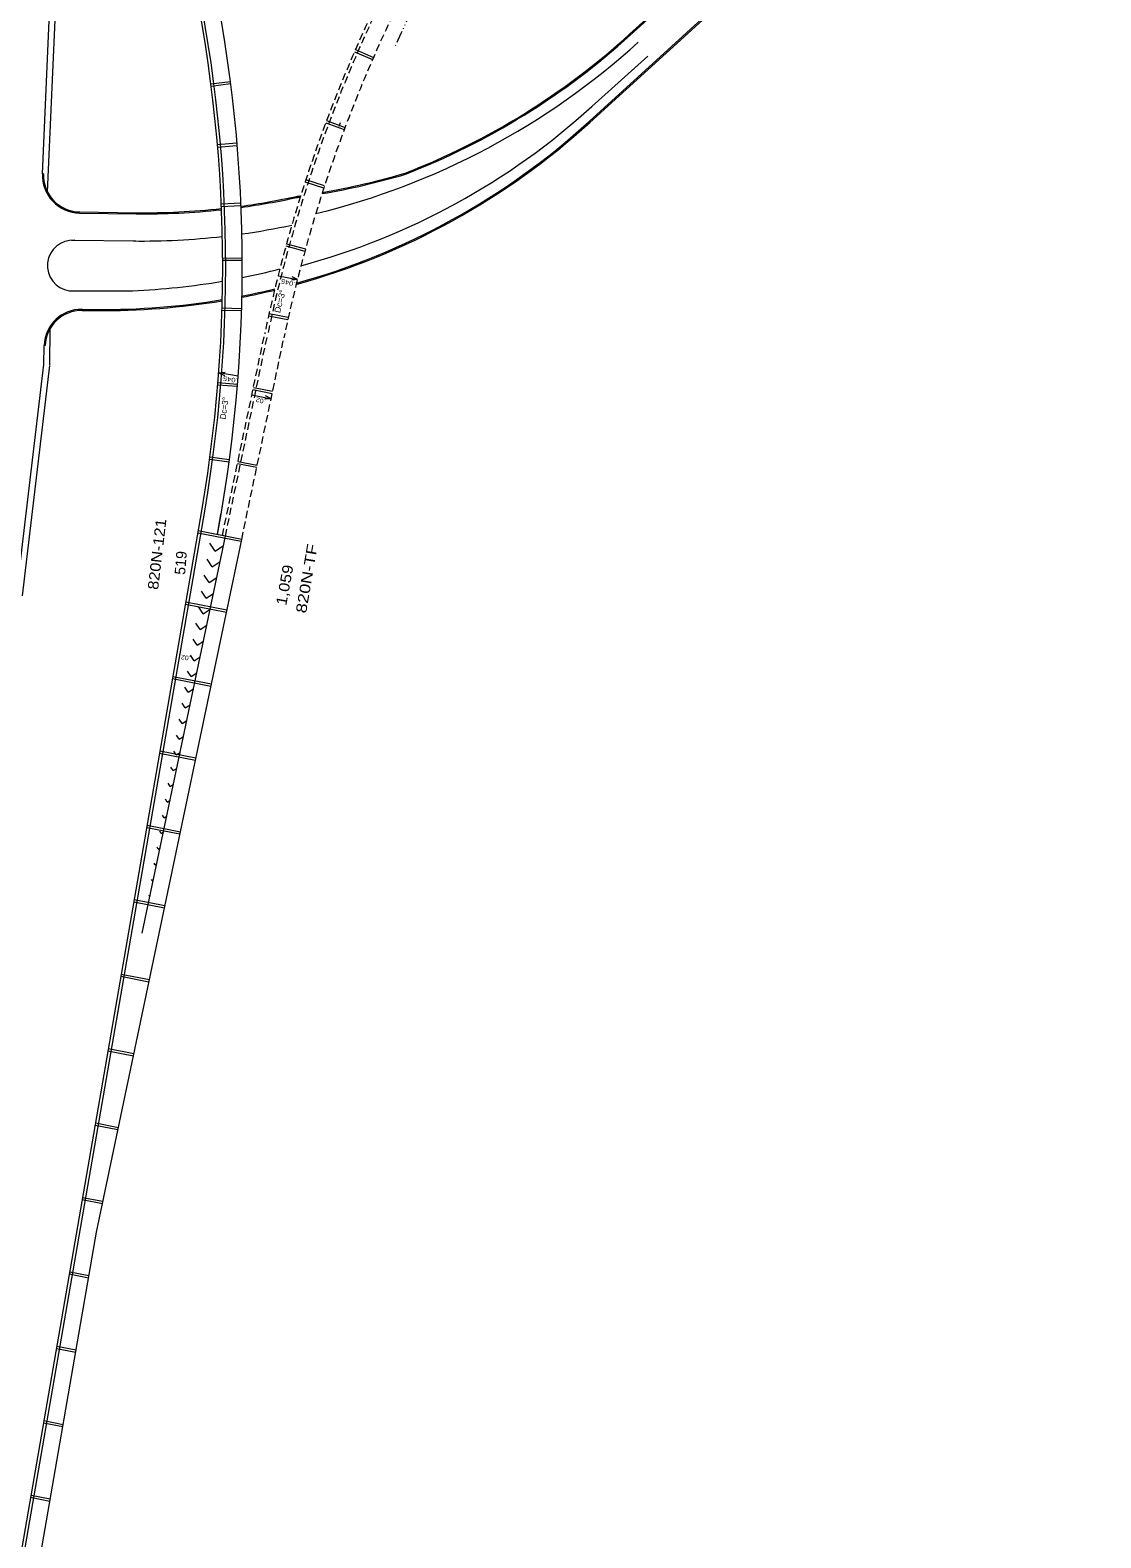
# Model space of a CAD drawing. Extents: x 2354993 to 2372084, y 6966390 to 6990057.
# Drawn here: x 2364667 to 2366085, y 6974745 to 6976742 of the extents above; entities that cross this region are included whole.
import ezdxf

# ---------------------------------------------------------------- set-up
doc = ezdxf.new("R2010")
doc.units = 0
doc.header["$LTSCALE"] = 3.2
doc.linetypes.add('DASH_DOUBLE_DOT', pattern=[9.2, 5, -1.2, 0.3, -1.2, 0.3, -1.2])
doc.linetypes.add('MEDIUM_DASHED', pattern=[4.5, 3, -1.5])
for name, color, linetype, lineweight in [('12', 7, 'Continuous', 13), ('13', 7, 'Continuous', 13), ('17', 7, 'Continuous', 13), ('19', 7, 'Continuous', 13), ('25', 7, 'Continuous', 13), ('4', 7, 'Continuous', 13), ('5', 7, 'Continuous', 13), ('60', 7, 'DASH_DOUBLE_DOT', 13), ('61', 7, 'Continuous', 13)]:
    doc.layers.add(name, color=color, linetype=linetype, lineweight=lineweight)

msp = doc.modelspace()

# ---------------------------------------------------------------- linework, layer by layer
at = {"layer": '12'}
for p, q in [((2365096.521, 6976713.391), (2365120.397, 6976703.098)), ((2365097.719, 6976716.141), (2365121.595, 6976705.847)), ((2364932.058, 6976673.71), (2364906.272, 6976670.388)), ((2364932.439, 6976670.735), (2364906.652, 6976667.414)), ((2365058.546, 6976619.394), (2365082.928, 6976610.363)), ((2365059.598, 6976622.202), (2365083.98, 6976613.172)), ((2365055.863, 6976532.894), (2365031.104, 6976540.83)), ((2365056.793, 6976535.746), (2365032.033, 6976543.683)), ((2365005.707, 6976456.21), (2365030.792, 6976449.371)), ((2365006.505, 6976459.1), (2365031.59, 6976452.262)), ((2364947.746, 6976439.942), (2364921.747, 6976439.789)), ((2364947.762, 6976436.943), (2364921.762, 6976436.79)), ((2364946.976, 6976373.133), (2364920.987, 6976373.885)), ((2364946.887, 6976370.135), (2364920.898, 6976370.888)), ((2365008.13, 6976358.355), (2364982.603, 6976363.334)), ((2365008.786, 6976361.284), (2364983.257, 6976366.263)), ((2364941.443, 6976272.877), (2364915.529, 6976274.989)), ((2364941.198, 6976269.888), (2364915.283, 6976271.999)), ((2364987.466, 6976260.5), (2364961.946, 6976265.478)), ((2364988.082, 6976263.437), (2364962.562, 6976268.415)), ((2364930.671, 6976173.053), (2364905.008, 6976176.492)), ((2364930.27, 6976170.081), (2364904.606, 6976173.52)), ((2364966.957, 6976162.616), (2364941.436, 6976167.593)), ((2364967.572, 6976165.553), (2364942.052, 6976170.53)), ((2364946.446, 6976064.731), (2364888.859, 6976075.962)), ((2364947.061, 6976067.668), (2364889.372, 6976078.919)), ((2364926.764, 6975970.796), (2364872.469, 6975981.384)), ((2364927.379, 6975973.733), (2364872.982, 6975984.341)), ((2364906.253, 6975872.912), (2364855.391, 6975882.83)), ((2364906.869, 6975875.849), (2364855.904, 6975885.787)), ((2364885.744, 6975775.027), (2364838.313, 6975784.277)), ((2364886.359, 6975777.964), (2364838.825, 6975787.232)), ((2364865.234, 6975677.145), (2364821.234, 6975685.724)), ((2364865.849, 6975680.081), (2364821.747, 6975688.681)), ((2364844.724, 6975579.26), (2364804.156, 6975587.171)), ((2364845.34, 6975582.197), (2364804.669, 6975590.128)), ((2364824.214, 6975481.376), (2364787.078, 6975488.619)), ((2364824.829, 6975484.312), (2364787.59, 6975491.573)), ((2364803.704, 6975383.491), (2364769.999, 6975390.064)), ((2364804.318, 6975386.428), (2364770.512, 6975393.02)), ((2364783.194, 6975285.607), (2364752.921, 6975291.511)), ((2364783.809, 6975288.544), (2364753.434, 6975294.468)), ((2364763.299, 6975190.66), (2364736.355, 6975195.914)), ((2364762.683, 6975187.724), (2364735.843, 6975192.958)), ((2364744.801, 6975092.383), (2364719.277, 6975097.36)), ((2364744.289, 6975089.427), (2364718.764, 6975094.404)), ((2364727.21, 6974990.872), (2364701.686, 6974995.85)), ((2364727.723, 6974993.831), (2364702.199, 6974998.809)), ((2364710.132, 6974892.321), (2364684.608, 6974897.298)), ((2364710.645, 6974895.277), (2364685.12, 6974900.253)), ((2364693.054, 6974793.767), (2364667.529, 6974798.744)), ((2364693.566, 6974796.725), (2364668.042, 6974801.701))]:
    msp.add_line(p, q, dxfattribs=at)
at = {"layer": '19'}
for p, q in [((2365021.106, 6976411.605), (2365012.825, 6976410.894)), ((2364916.883, 6976288.383), (2364925.161, 6976289.131)), ((2364986.024, 6976253.941), (2364977.743, 6976253.23))]:
    msp.add_line(p, q, dxfattribs=at)
for points in [[(2364995.797, 6976416.524), (2365021.106, 6976411.605), (2365013.699, 6976415.362)], [(2364942.214, 6976283.578), (2364916.883, 6976288.383), (2364924.307, 6976284.659)], [(2364960.715, 6976258.86), (2364986.024, 6976253.941), (2364978.617, 6976257.698)]]:
    msp.add_lwpolyline(points, dxfattribs=at)
at = {"layer": '25'}
msp.add_line((2364685.177, 6976299.01), (2364685.261, 6976324.55), dxfattribs=at)
at = {"layer": '4'}
msp.add_arc((2367020.832, 6975885.878), 2076.901, 159.32699, 159.47101, dxfattribs=at)
at = {"layer": '5'}
for p, q in [((2364683.134, 6976551.86), (2364717.405, 6977340.009)), ((2364690.072, 6976527.283), (2364724.81, 6977326.163)), ((2365461.706, 6976735.455), (2365523.82, 6976791.997)), ((2365407.189, 6976620.909), (2365556.136, 6976756.497)), ((2365408.199, 6976619.8), (2365557.146, 6976755.388)), ((2365410.613, 6976640.666), (2365484.741, 6976707.345)), ((2364684.633, 6976551.795), (2364683.134, 6976551.86)), ((2364732.47, 6976499.692), (2364807.291, 6976498.769)), ((2364732.489, 6976501.192), (2364807.31, 6976500.269)), ((2364721.568, 6976463.823), (2364806.847, 6976462.772)), ((2364718.768, 6976396.876), (2364802.345, 6976396.919)), ((2364735.68, 6976370.876), (2364755.262, 6976370.688)), ((2364735.694, 6976372.376), (2364755.276, 6976372.188)), ((2364693.177, 6976298.984), (2364693.335, 6976346.84)), ((2364686.76, 6976324.485), (2364685.261, 6976324.55)), ((2364648.854, 6975993.703), (2364685.177, 6976299.01)), ((2364656.798, 6975992.758), (2364693.121, 6976298.065)), ((2364588.065, 6974339.557), (2364894.105, 6976105.613)), ((2364592.006, 6974338.873), (2364898.046, 6976104.929)), ((2364914.925, 6976074.108), (2364919.617, 6976101.182)), ((2364915.004, 6976073.933), (2364919.724, 6976101.173)), ((2364925.467, 6976071.879), (2364907.042, 6976075.473)), ((2364754.787, 6975150.037), (2364947.062, 6976067.668)), ((2364815.346, 6975546.328), (2364925.467, 6976071.879)), ((2364912.131, 6976052.127), (2364904.844, 6976062.789)), ((2364912.131, 6976052.127), (2364922.841, 6976059.346)), ((2364908.156, 6976031.357), (2364901.168, 6976041.581)), ((2364908.156, 6976031.357), (2364918.427, 6976038.279)), ((2364904.183, 6976010.591), (2364897.494, 6976020.377)), ((2364904.183, 6976010.591), (2364914.013, 6976017.217)), ((2364900.209, 6975989.825), (2364893.819, 6975999.173)), ((2364900.209, 6975989.825), (2364909.599, 6975996.153)), ((2364896.234, 6975969.053), (2364890.144, 6975977.963)), ((2364896.234, 6975969.053), (2364905.185, 6975975.086)), ((2364892.261, 6975948.288), (2364886.47, 6975956.761)), ((2364892.261, 6975948.288), (2364900.772, 6975954.024)), ((2364888.287, 6975927.519), (2364882.795, 6975935.553)), ((2364884.313, 6975906.753), (2364879.12, 6975914.349)), ((2364888.287, 6975927.519), (2364896.358, 6975932.96)), ((2364884.313, 6975906.753), (2364891.945, 6975911.897)), ((2364880.339, 6975885.984), (2364875.446, 6975893.143)), ((2364880.339, 6975885.984), (2364887.531, 6975890.832)), ((2364876.366, 6975865.217), (2364871.771, 6975871.938)), ((2364876.366, 6975865.217), (2364883.117, 6975869.767)), ((2364872.392, 6975844.451), (2364868.097, 6975850.735)), ((2364872.392, 6975844.451), (2364878.704, 6975848.705)), ((2364868.418, 6975823.684), (2364864.422, 6975829.53)), ((2364868.418, 6975823.684), (2364874.291, 6975827.641)), ((2364864.443, 6975802.913), (2364860.747, 6975808.321)), ((2364864.443, 6975802.913), (2364869.877, 6975806.575)), ((2364860.47, 6975782.147), (2364857.072, 6975787.118)), ((2364860.47, 6975782.147), (2364865.463, 6975785.513)), ((2364856.495, 6975761.375), (2364853.396, 6975765.908)), ((2364856.495, 6975761.375), (2364861.049, 6975764.445)), ((2364852.52, 6975740.604), (2364849.721, 6975744.699)), ((2364852.52, 6975740.604), (2364856.635, 6975743.379)), ((2364848.547, 6975719.835), (2364846.046, 6975723.492)), ((2364848.547, 6975719.835), (2364852.22, 6975722.312)), ((2364844.572, 6975699.066), (2364842.372, 6975702.285)), ((2364844.572, 6975699.066), (2364847.806, 6975701.246)), ((2364840.598, 6975678.295), (2364838.696, 6975681.077)), ((2364840.598, 6975678.295), (2364843.392, 6975680.179)), ((2364836.623, 6975657.525), (2364835.021, 6975659.869)), ((2364836.623, 6975657.525), (2364838.978, 6975659.113)), ((2364832.649, 6975636.755), (2364831.346, 6975638.661)), ((2364832.649, 6975636.755), (2364834.564, 6975638.047)), ((2364828.675, 6975615.989), (2364827.672, 6975617.456)), ((2364828.675, 6975615.989), (2364830.151, 6975616.983)), ((2364824.7, 6975595.216), (2364823.996, 6975596.246)), ((2364824.7, 6975595.216), (2364825.736, 6975595.914)), ((2364613.575, 6974335.122), (2364754.814, 6975150.165))]:
    msp.add_line(p, q, dxfattribs=at)
at = {"layer": '5', "linetype": 'MEDIUM_DASHED'}
for p, q in [((2364925.467, 6976071.879), (2364981.448, 6976339.048)), ((2364947.062, 6976067.668), (2365002.98, 6976334.537))]:
    msp.add_line(p, q, dxfattribs=at)
at = {"layer": '5'}
msp.add_lwpolyline([(2365460.696, 6976736.564), (2365522.81, 6976793.106), (2365788.855, 6977035.453)], dxfattribs=at)
at = {"layer": '5', "linetype": 'MEDIUM_DASHED'}
msp.add_lwpolyline([(2364921.553, 6976072.7), (2364977.534, 6976339.869), (2364977.533, 6976339.868)], dxfattribs=at)
for radius, start in [(1927.859, 114.19653), (1923.859, 114.19652), (1901.859, 114.19652)]:
    msp.add_arc((2366864.416, 6975944.503), radius, start, 168.16581, dxfattribs=at)
at = {"layer": '5'}
for centre, radius, start, end in [((2363030.028, 6976428.641), 1917.859, 350.16881, 38.12295), ((2363030.028, 6976428.641), 1891.859, 350.16881, 38.12295), ((2363030.028, 6976428.641), 1895.859, 350.16881, 38.12295), ((2364818.89, 6977441.63), 953.43, 291.18831, 312.311), ((2364818.89, 6977441.63), 954.93, 291.18831, 312.311), ((2364813.366, 6977450.171), 978.93, 283.69992, 312.311), ((2364783.944, 6977329.083), 930.93, 285.04443, 312.3117), ((2364764.362, 6977327.074), 956.43, 285.45314, 312.3117), ((2364764.362, 6977327.074), 954.93, 285.50407, 312.3117), ((2364733.087, 6976549.688), 50, 177.51014, 269.29335), ((2364733.087, 6976549.688), 48.5, 177.51014, 269.29335), ((2364895.014, 6977455.068), 943, 279.67326, 286.57564), ((2364895.014, 6977455.068), 941.5, 279.72076, 286.57564), ((2364818.89, 6977441.63), 941.43, 277.76598, 282.30884), ((2364818.89, 6977441.63), 942.93, 277.75738, 282.30884), ((2364895.014, 6977455.068), 941.5, 277.61057, 277.95298), ((2364895.014, 6977455.068), 943, 277.61057, 277.90976), ((2364818.89, 6977441.63), 942.93, 269.29528, 276.17227), ((2364818.89, 6977441.63), 941.43, 269.29528, 276.17843), ((2364815.037, 6977405.676), 942.93, 278.06261, 282.15306), ((2364723.307, 6976430.218), 33.65, 85.61434, 262.24679), ((2364815.037, 6977405.676), 942.93, 269.29632, 276.47397), ((2364764.362, 6977327.074), 930.93, 281.35975, 284.51035), ((2364764.362, 6977327.074), 930.93, 272.3384, 279.72926), ((2364764.362, 6977327.074), 956.43, 281.03036, 283.68281), ((2364764.362, 6977327.074), 954.93, 281.04984, 283.72929), ((2364764.362, 6977327.074), 956.43, 269.45448, 279.44073), ((2364764.362, 6977327.074), 954.93, 269.45448, 279.45787), ((2364735.214, 6976322.378), 50, 89.44996, 177.51015), ((2364735.214, 6976322.378), 48.5, 89.44996, 177.51015)]:
    msp.add_arc(centre, radius, start, end, dxfattribs=at)
at = {"layer": '60'}
msp.add_arc((2366864.416, 6975944.503), 1881.859, 114.65077, 155.69784, dxfattribs=at)
at = {"layer": '61'}
for p, q in [((2364914.843, 6976590.548), (2364940.248, 6976592.683)), ((2364915.136, 6976587.06), (2364940.541, 6976589.195)), ((2364919.944, 6976512.037), (2364945.924, 6976513.135)), ((2364920.092, 6976508.54), (2364946.072, 6976509.638))]:
    msp.add_line(p, q, dxfattribs=at)

# ---------------------------------------------------------------- texts
at = {"layer": '13'}
for s, rotation, width, p in [('820N-121', 83.24, 1.15, (2364836.339, 6976000.314)), ('820N-TF', 80.363, 1.25, (2365032.358, 6975969.107)), ('1,059', 79.691, 1.15, (2365006.072, 6975979.488))]:
    msp.add_text(s, height=14, rotation=rotation, dxfattribs=dict(at, width=width)).set_placement(p)
msp.add_text('519', height=14, rotation=85.353, dxfattribs=at).set_placement((2364872.068, 6976020.364))
at = {"layer": '17', "width": 1.05}
msp.add_text('Dc=3°', height=8, rotation=75.446, dxfattribs=at).set_placement((2364997.721, 6976366.904))
at = {"layer": '17'}
msp.add_text('Dc=3°', height=8, rotation=82.162, dxfattribs=at).set_placement((2364925.831, 6976226.161))
at = {"layer": '19'}
for s, height, rotation, width, p in [('.045', 5.999, 165.77, 1.25, (2365018.815, 6976408.07)), ('.045', 6, 169.85, 1.25, (2364942.138, 6976280.612)), ('.02', 6, 165.493, 1.2, (2364979.429, 6976252.509)), ('.02', 6, 169.821, 1.15, (2364879.893, 6975912.726))]:
    msp.add_text(s, height=height, rotation=rotation, dxfattribs=dict(at, width=width)).set_placement(p)

doc.saveas('drawing.dxf')
